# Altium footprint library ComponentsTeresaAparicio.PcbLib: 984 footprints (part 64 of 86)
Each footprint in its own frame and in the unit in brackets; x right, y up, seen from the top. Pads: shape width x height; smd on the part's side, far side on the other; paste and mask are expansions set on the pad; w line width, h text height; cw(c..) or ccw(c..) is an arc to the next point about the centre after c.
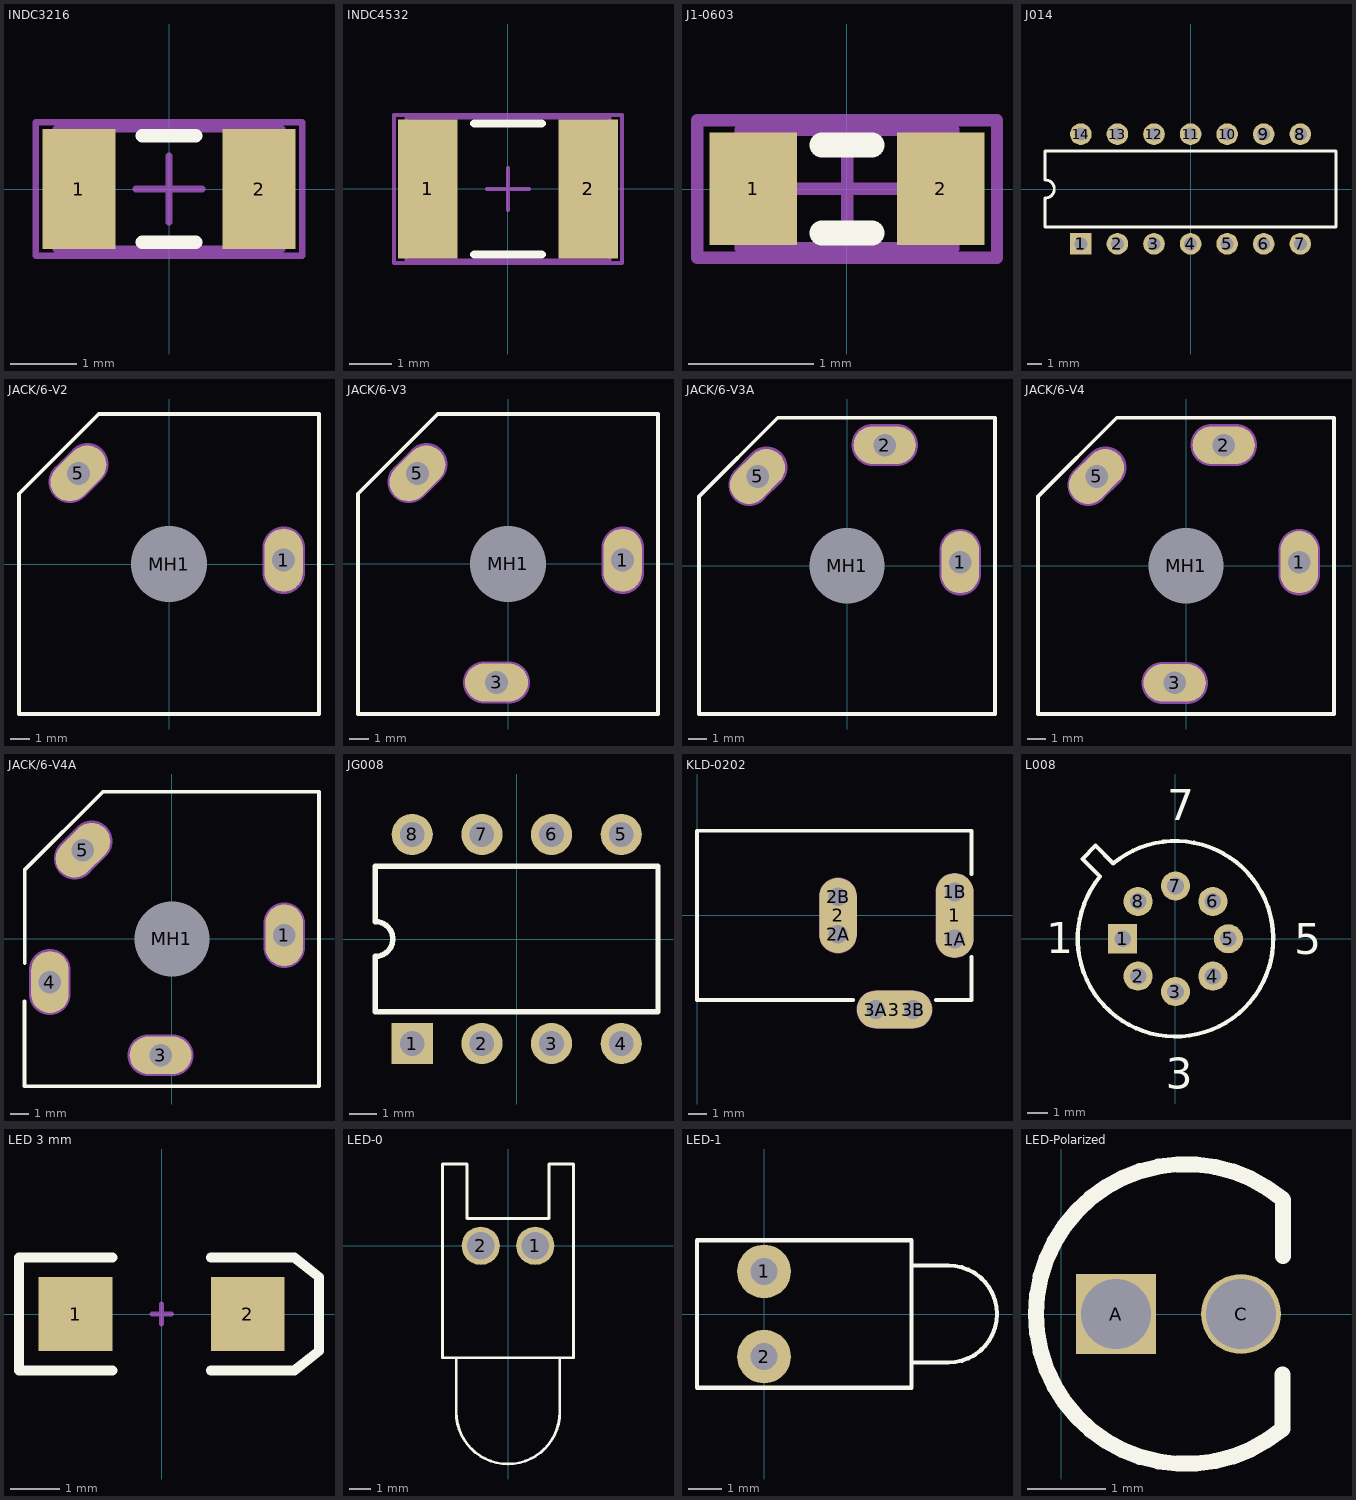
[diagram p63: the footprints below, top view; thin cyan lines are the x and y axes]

## INDC3216 [mm] "Chip Inductor, Body 3.2x1.6mm, IPC High Density"
height 0.55
pads (2):
  rect 1.1x1.8 smd: 1(-1.35,0) 2(1.35,0)
Top Overlay:
  lines w0.2: -0.4,-0.8 0.4,-0.8 ; -0.4,0.8 0.4,0.8
Mechanical 13:
  lines w0.1: -1.7,-0.9 1.7,-0.9 1.7,0.9 -1.7,0.9 -1.7,-0.9
Mechanical 15:
  lines w0.1: -0.5,0 0.5,0 ; 0,-0.5 0,0.5 ; -2,-1 2,-1 2,1 -2,1 -2,-1
3D body: height 0.55, standoff 0, extent -1.7,-0.9 1.7,0.9

## INDC4532 [mm] "Chip Inductor, Body 4.5x3.2mm, IPC High Density"
height 0.55
pads (2):
  rect 1.4x3.3 smd: 1(-1.9,0) 2(1.9,0)
Top Overlay:
  lines w0.2: -0.8,-1.55 0.8,-1.55 ; -0.8,1.55 0.8,1.55
Mechanical 13:
  lines w0.1: -2.4,-1.7 2.4,-1.7 2.4,1.7 -2.4,1.7 -2.4,-1.7
Mechanical 15:
  lines w0.1: -0.5,0 0.5,0 ; 0,-0.5 0,0.5 ; -2.7,-1.75 2.7,-1.75 2.7,1.75 -2.7,1.75 -2.7,-1.75
3D body: height 0.55, standoff 0, extent -2.4,-1.7 2.4,1.7

## J1-0603 [mm] "Chip Resistor, Body 1.6x0.8mm, IPC High Density"
height 0.9
pads (2):
  rect 0.7x0.9 smd: 1(-0.75,0) 2(0.75,0)
Top Overlay:
  lines w0.2: -0.2,-0.35 0.2,-0.35 ; -0.2,0.35 0.2,0.35
Mechanical 13:
  lines w0.1: -0.85,-0.475 0.85,-0.475 0.85,0.475 -0.85,0.475 -0.85,-0.475
Mechanical 15:
  lines w0.1: -0.475,0 0.475,0 ; 0,-0.475 0,0.475 ; -1.2,-0.55 1.2,-0.55 1.2,0.55 -1.2,0.55 -1.2,-0.55
3D body: height 0.9, standoff 0, extent -0.85,-0.475 0.85,0.475

## J014 [mm] "DIP; 14 Leads; Row Spacing 7.62 mm; Pitch 2.54 mm"
height 5.08
pads (14):
  rect 1.5x1.5 hole 0.9: 1(-7.62,-3.81)
  round 1.5 hole 0.9: 2(-5.08,-3.81) 3(-2.54,-3.81) 4(0,-3.81) 5(2.54,-3.81) 6(5.08,-3.81) 7(7.62,-3.81) 8(7.62,3.81) 9(5.08,3.81) 10(2.54,3.81) 11(0,3.81) 12(-2.54,3.81) 13(-5.08,3.81) 14(-7.62,3.81)
Top Overlay:
  lines w0.2: -10.1,-2.65 -10.1,-0.635 ccw(c-10.1,0) -10.1,0.635 -10.1,2.65 10.1,2.65 10.1,-2.65 -10.1,-2.65

## JACK/6-V2 [mm] "Connector; Jack Socket, 1/4\" [6.5mm], Thru-Hole, 2 Position, Vertical, Body 15.7 x 15.7 x 31 mm (WxTxH)"
height 31.1
pads (3):
  oval 2x3.3 hole 1.2: 1(6,0.2)
  oval 2x3.3 hole 1.2 rot 135: 5(-4.738,4.738)
  round 3.7 hole 4: MH1(0,0)
Top Overlay:
  lines w0.2: -7.85,-7.85 7.85,-7.85 7.85,7.85 -3.675,7.85 -7.85,3.675 -7.85,-7.85
Mechanical 1:
  lines w1.2: -5.185,4.295 -4.266,5.214 ; 6,-0.45 6,0.85
  text "Alert PCB fab to slot details" at -7.9,9.66 h0.3
  text "Slot 1.2x2.5mm, PTH" at -7.9,9.16 h0.3
  text "Assign keep-out area to slot" at -7.9,10.16 h0.3
  text "Mech 1 - Slot cut-out" at -7.9,8.66 h0.3
  text "Mech 2 - Clearance, move to internal plane if present" at -7.9,8.16 h0.3
Mechanical 2:
  lines w2.216: -5.185,4.295 -4.266,5.214 ; 6,-0.45 6,0.85

## JACK/6-V3 [mm] "Connector; Jack Socket, 1/4\" [6.5mm], Thru-Hole, 3 Position, Vertical, Body 15.7 x 15.7 x 31 mm (WxTxH)"
height 31.1
pads (4):
  oval 2x3.3 hole 1.2: 1(6,0.2)
  oval 3.3x2 hole 1.2: 3(-0.6,-6.2)
  oval 2x3.3 hole 1.2 rot 135: 5(-4.738,4.738)
  round 3.7 hole 4: MH1(0,0)
Top Overlay:
  lines w0.2: -7.85,-7.85 -7.85,3.675 -3.675,7.85 7.85,7.85 7.85,-7.85 -7.85,-7.85
Mechanical 1:
  lines w1.2: -5.185,4.295 -4.266,5.214 ; -1.25,-6.2 0.05,-6.2 ; 6,-0.45 6,0.85
  text "Mech 2 - Clearance, move to internal plane if present" at -7.9,8.16 h0.3
  text "Mech 1 - Slot cut-out" at -7.9,8.66 h0.3
  text "Assign keep-out area to slot" at -7.9,10.16 h0.3
  text "Slot 1.2x2.5mm, PTH" at -7.9,9.16 h0.3
  text "Alert PCB fab to slot details" at -7.9,9.66 h0.3
Mechanical 2:
  lines w2.216: -5.185,4.295 -4.266,5.214 ; -1.25,-6.2 0.05,-6.2 ; 6,-0.45 6,0.85

## JACK/6-V3A [mm] "Connector; Jack Socket, 1/4\" [6.5mm], Thru-Hole, 3 Position, Vertical, Body 15.7 x 15.7 x 31 mm (WxTxH)"
height 31.1
pads (4):
  oval 2x3.3 hole 1.2: 1(6,0.2)
  oval 3.3x2 hole 1.2: 2(2,6.4)
  oval 2x3.3 hole 1.2 rot 135: 5(-4.738,4.738)
  round 3.7 hole 4: MH1(0,0)
Top Overlay:
  lines w0.2: -7.85,-7.85 7.85,-7.85 7.85,7.85 -3.675,7.85 -7.85,3.675 -7.85,-7.85
Mechanical 1:
  lines w1.2: -5.185,4.295 -4.266,5.214 ; 1.35,6.4 2.65,6.4 ; 6,-0.45 6,0.85
  text "Mech 2 - Clearance, move to internal plane if present" at -7.9,8.16 h0.3
  text "Mech 1 - Slot cut-out" at -7.9,8.66 h0.3
  text "Assign keep-out area to slot" at -7.9,10.16 h0.3
  text "Slot 1.2x2.5mm, PTH" at -7.9,9.16 h0.3
  text "Alert PCB fab to slot details" at -7.9,9.66 h0.3
Mechanical 2:
  lines w2.216: -5.185,4.295 -4.266,5.214 ; 1.35,6.4 2.65,6.4 ; 6,-0.45 6,0.85

## JACK/6-V4 [mm] "Connector; Jack Socket, 1/4\" [6.5mm], Thru-Hole, 4 Position, Vertical, Body 15.7 x 15.7 x 31 mm (WxTxH)"
height 31.1
pads (5):
  oval 2x3.3 hole 1.2: 1(6,0.2)
  oval 3.3x2 hole 1.2: 2(2,6.4) 3(-0.6,-6.2)
  oval 2x3.3 hole 1.2 rot 135: 5(-4.738,4.738)
  round 3.7 hole 4: MH1(0,0)
Top Overlay:
  lines w0.2: -7.85,-7.85 7.85,-7.85 7.85,7.85 -3.675,7.85 -7.85,3.675 -7.85,-7.85
Mechanical 1:
  lines w1.2: -5.185,4.295 -4.266,5.214 ; -1.25,-6.2 0.05,-6.2 ; 1.35,6.4 2.65,6.4 ; 6,-0.45 6,0.85
  text "Mech 2 - Clearance, move to internal plane if present" at -7.9,8.16 h0.3
  text "Mech 1 - Slot cut-out" at -7.9,8.66 h0.3
  text "Assign keep-out area to slot" at -7.9,10.16 h0.3
  text "Slot 1.2x2.5mm, PTH" at -7.9,9.16 h0.3
  text "Alert PCB fab to slot details" at -7.9,9.66 h0.3
Mechanical 2:
  lines w2.216: -5.185,4.295 -4.266,5.214 ; -1.25,-6.2 0.05,-6.2 ; 1.35,6.4 2.65,6.4 ; 6,-0.45 6,0.85

## JACK/6-V4A [mm] "Connector; Jack Socket, 1/4\" [6.5mm], Thru-Hole, 4 Position, Vertical, Body 15.7 x 15.7 x 31 mm (WxTxH)"
height 31.1
pads (5):
  oval 2x3.3 hole 1.2: 1(6,0.2) 4(-6.5,-2.3)
  oval 3.3x2 hole 1.2: 3(-0.6,-6.2)
  oval 2x3.3 hole 1.2 rot 135: 5(-4.738,4.738)
  round 3.7 hole 4: MH1(0,0)
Top Overlay:
  lines w0.2: -7.85,-3.32 -7.85,-7.85 7.85,-7.85 7.85,7.85 -3.675,7.85 -7.85,3.675 -7.85,-1.28
Mechanical 1:
  lines w1.2: -6.5,-2.95 -6.5,-1.65 ; -5.185,4.295 -4.266,5.214 ; -1.25,-6.2 0.05,-6.2 ; 6,-0.45 6,0.85
  text "Alert PCB fab to slot details" at -7.9,9.66 h0.3
  text "Slot 1.2x2.5mm, PTH" at -7.9,9.16 h0.3
  text "Assign keep-out area to slot" at -7.9,10.16 h0.3
  text "Mech 1 - Slot cut-out" at -7.9,8.66 h0.3
  text "Mech 2 - Clearance, move to internal plane if present" at -7.9,8.16 h0.3
Mechanical 2:
  lines w2.216: -6.5,-2.95 -6.5,-1.65 ; -5.185,4.295 -4.266,5.214 ; -1.25,-6.2 0.05,-6.2 ; 6,-0.45 6,0.85

## JG008 [mm] "DIP; 8 Leads; Row Spacing 7.62 mm; Pitch 2.54 mm"
height 5.08
pads (8):
  rect 1.5x1.5 hole 0.9: 1(-3.81,-3.81)
  round 1.5 hole 0.9: 2(-1.27,-3.81) 3(1.27,-3.81) 4(3.81,-3.81) 5(3.81,3.81) 6(1.27,3.81) 7(-1.27,3.81) 8(-3.81,3.81)
Top Overlay:
  lines w0.2: -5.15,-2.65 5.15,-2.65 5.15,2.65 -5.15,2.65 -5.15,0.635 cw(c-5.15,0) -5.15,-0.635 -5.15,-2.65

## KLD-0202 [mm] "DC Power Jack, 2.5mm, KLD Series, PCB Mount"
pads (9):
  oval 2x4.5 all layers, no hole: 1(13.7,0)
  round 1.5 hole 1: 1A(13.7,-1.25) 1B(13.7,1.25) 2A(7.5,-1) 2B(7.5,1) 3A(9.5,-5) 3B(11.5,-5)
  oval 2x4 all layers, no hole: 2(7.5,0)
  oval 4x2 all layers, no hole: 3(10.5,-5)
Top Overlay:
  lines w0.2: 8.3,-4.5 0,-4.5 0,4.5 14.6,4.5 14.6,2.2 ; 12.7,-4.5 14.6,-4.5 14.6,-2.2
Mechanical 1:
  lines w1: 7.5,-1 7.5,1 ; 9.5,-5 11.5,-5 ; 13.7,-1.25 13.7,1.25
  text "Alert PCB fab to slot details" at 0.286,6.066 h0.3
  text "Assign keep-out area to slot" at 0.286,6.566 h0.3
  text "Mech 1 - Slot cut-out" at 0.286,5.566 h0.3
  text "Mech 2 - Clearance, move to internal plane if present" at 0.286,5.066 h0.3
Mechanical 2:
  lines w2.016: 7.5,-1 7.5,1 ; 9.5,-5 11.5,-5 ; 13.7,-1.25 13.7,1.25

## L008 [mm] "Can; 8 Leads; Pin Circle Dia. 5.08 mm; Lead Dia. 0.48 mm (max)"
height 4.7
pads (8):
  rect 1.4x1.4 hole 0.8: 1(-2.54,0)
  round 1.4 hole 0.8: 2(-1.796,-1.796) 3(0,-2.54) 4(1.796,-1.796) 5(2.54,0) 6(1.796,1.796) 7(0,2.54) 8(-1.796,1.796)
Top Overlay:
  lines w0.2: -4.475,3.838 -3.838,4.475 -2.99,3.626 cw(c0,0) -3.626,2.99 -4.475,3.838
  text "1" at -6.201,-0.697 h1.5
  text "3" at -0.469,-7.22 h1.5
  text "5" at 5.713,-0.751 h1.5
  text "7" at -0.397,5.7 h1.5

## LED 3 mm [mm] "SMT LED; 2 Flat Leads"
height 1.2
pads (2):
  rect 1.5x1.5 smd: 1(-1.75,0) 2(1.75,0)
Top Overlay:
  lines w0.2: -1,-1.15 -2.9,-1.15 -2.9,1.15 -1,1.15 ; 1,-1.15 2.7,-1.15 3.2,-0.75 3.2,0.75 2.7,1.15 1,1.15
Mechanical 1:
  lines w0.1: -0.2,0 0.2,0 ; 0,-0.2 0,0.2
3D body: height 27.84, standoff -3.81, extent -2,-2.2 1.52,1.8

## LED-0 [mil] "LED; 2 Leads"
pads (2):
  round 70 hole 50: 1(50,0) 2(-50,0)
Top Overlay:
  lines w5: -95,-205 -95,-305 ccw(c0,-305) 95,-305 95,-205 ; -120,-205 -120,150 -75,150 -75,50 75,50 75,150 120,150 120,-205 -120,-205
3D body: height 646.06, standoff -600, extent -348.73,-73.73 -210.14,83.75

## LED-1 [mm] "LED; 2 Leads"
pads (2):
  round 1.6 hole 0.8: 1(0,1.27) 2(0,-1.27)
Top Overlay:
  lines w0.127: 4.4,-1.45 5.5,-1.45 ccw(c5.5,0) 5.5,1.45 4.4,1.45 ; -2,-2.2 4.4,-2.2 4.4,2.2 -2,2.2 -2,-2.2

## LED-Polarized [mil]
pads (2):
  rect 40x40 hole 35: A(27.56,0)
  round 40 hole 35: C(90,0)
Top Overlay:
  lines w8: 110.71,-30.19 110.71,-57.45 cw(c62.5,0) 110.71,57.45 ; 111,29 111,56.95
3D body: height 237.17, standoff -18.74, extent -13.03,-68.9 118.11,68.9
